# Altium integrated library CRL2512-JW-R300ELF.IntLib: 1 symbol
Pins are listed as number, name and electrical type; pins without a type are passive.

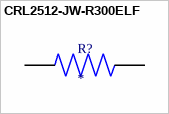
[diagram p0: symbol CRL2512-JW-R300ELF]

## CRL2512-JW-R300ELF
designator R?
Res Thick Film 2512 0.3 Ohm 5% 1W Â±200ppm/Â°C Molded SMD SMD Embossed Plastic T/R; MF: Bourns; MP: CRL2512-JW-R300ELF
footprint RESC6331X70N
pins: 1, 2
